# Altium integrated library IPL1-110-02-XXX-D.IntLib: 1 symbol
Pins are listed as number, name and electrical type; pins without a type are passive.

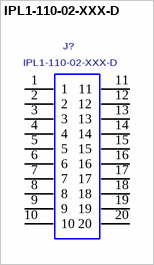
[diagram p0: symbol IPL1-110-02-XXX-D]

## IPL1-110-02-XXX-D
designator J?
0.100" DOUBLE ROW TERMINAL ASSEMBLY.; MANUFACTURER: SAMTEC
footprint IPL1-110-02-XXX-D
pins: 1, 2, 3, 4, 5, 6, 7, 8, 9, 10, 11, 12, 13, 14, 15, 16, 17, 18, 19, 20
